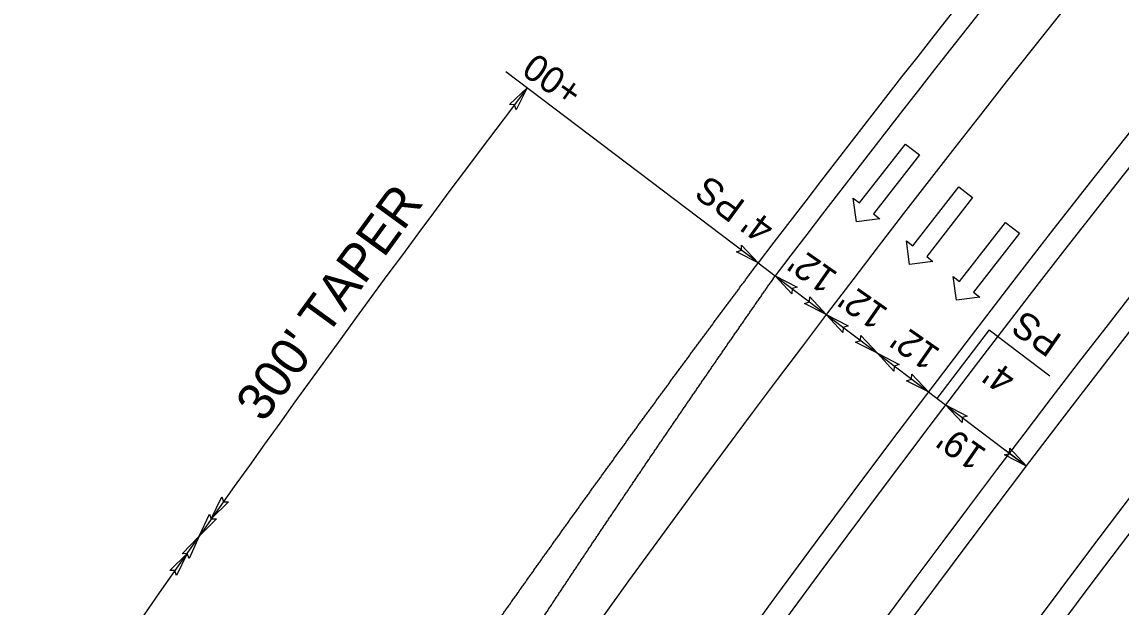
# Model space of a CAD drawing. Extents: x 2389099 to 2405615, y 552200 to 573532.
# Drawn here: x 2400552.8 to 2400758.8, y 569760.3 to 569869.9 of the extents above; entities that cross this region are included whole.
import ezdxf

# ---------------------------------------------------------------- set-up
doc = ezdxf.new("R2010")
doc.units = 0
for name, color, linetype in [('Prop Cable Guiderail Single Face', 7, 'Continuous'), ('Prop Dimension', 7, 'Continuous'), ('Prop Dimension Text', 7, 'Continuous'), ('Prop EOT', 7, 'Continuous'), ('Prop Horizontal Alignment', 7, 'Continuous'), ('Prop Horizontal Alignment Tick Small', 7, 'Continuous'), ('Prop Lane Arrow Through CELL', 7, 'Continuous'), ('Prop Lane Lines', 7, 'Continuous')]:
    doc.layers.add(name, color=color, linetype=linetype)

msp = doc.modelspace()

# ---------------------------------------------------------------- linework, layer by layer
at = {"layer": 'Prop Cable Guiderail Single Face'}
msp.add_arc((2403051.7, 568034.46), 2904, 119.41161, 162.0892, dxfattribs=at)
at = {"layer": 'Prop Dimension'}
for p, q in [((2400690.71, 569824.73), (2400643.46, 569860.55)), ((2400690.71, 569824.73), (2400693.89, 569822.31)), ((2400693.89, 569822.31), (2400703.45, 569815.06)), ((2400703.45, 569815.06), (2400713.02, 569807.81)), ((2400733.93, 569812.21), (2400724.17, 569799.35)), ((2400733.93, 569812.21), (2400745.34, 569803.56)), ((2400713.02, 569807.81), (2400722.58, 569800.56)), ((2400722.58, 569800.56), (2400725.77, 569798.14)), ((2400725.77, 569798.14), (2400740.91, 569786.66))]:
    msp.add_line(p, q, dxfattribs=at)
for points in [[(2400644.12, 569854.41), (2400647.45, 569857.52), (2400645.36, 569853.43), (2400645.07, 569854.38)], [(2400687.59, 569828.06), (2400690.71, 569824.73), (2400686.62, 569826.82), (2400687.56, 569827.11)], [(2400697.01, 569818.97), (2400693.89, 569822.31), (2400697.98, 569820.21), (2400697.04, 569819.92)], [(2400700.34, 569818.4), (2400703.45, 569815.06), (2400699.37, 569817.16), (2400700.31, 569817.45)], [(2400706.57, 569811.72), (2400703.45, 569815.06), (2400707.54, 569812.96), (2400706.6, 569812.67)], [(2400709.9, 569811.15), (2400713.02, 569807.81), (2400708.93, 569809.91), (2400709.87, 569810.2)], [(2400716.13, 569804.47), (2400713.02, 569807.81), (2400717.11, 569805.71), (2400716.16, 569805.42)], [(2400719.46, 569803.9), (2400722.58, 569800.56), (2400718.49, 569802.66), (2400719.43, 569802.95)], [(2400728.88, 569794.81), (2400725.77, 569798.14), (2400729.85, 569796.05), (2400728.91, 569795.76)], [(2400737.79, 569790), (2400740.91, 569786.66), (2400736.82, 569788.76), (2400737.76, 569789.05)], [(2400591.53, 569779.99), (2400588.3, 569776.76), (2400590.26, 569780.92), (2400590.58, 569779.99)], [(2400589.25, 569776.77), (2400586.02, 569773.54), (2400587.98, 569777.69), (2400588.3, 569776.76)], [(2400582.85, 569770.25), (2400586.02, 569773.54), (2400584.14, 569769.35), (2400583.8, 569770.27)], [(2400580.52, 569767.1), (2400583.8, 569770.27), (2400581.77, 569766.15), (2400581.47, 569767.08)]]:
    msp.add_lwpolyline(points, close=True, dxfattribs=at)
msp.add_arc((2403051.7, 568034.46), 3017.28, 142.82813, 148.75528, dxfattribs=at)
at = {"layer": 'Prop EOT'}
for radius, start, end in [(2923, 119.41161, 180.94658), (2919, 119.41161, 162.43732), (2881, 119.41161, 165.38993), (2877, 119.41161, 180.94658), (2963, 136.77855, 142.82813), (2959, 136.77855, 142.82813)]:
    msp.add_arc((2403051.7, 568034.46), radius, start, end, dxfattribs=at)
for points in [[(2400654.5, 569775.27), (2400654.98, 569775.94), (2400655.46, 569776.61), (2400655.94, 569777.28), (2400656.43, 569777.95), (2400656.91, 569778.63), (2400657.39, 569779.3), (2400657.88, 569779.98), (2400658.36, 569780.65), (2400658.85, 569781.32), (2400659.33, 569781.99), (2400659.81, 569782.67), (2400660.3, 569783.34), (2400660.78, 569784.01), (2400661.27, 569784.68), (2400661.75, 569785.35), (2400662.24, 569786.02), (2400662.72, 569786.69), (2400663.21, 569787.36), (2400663.7, 569788.04), (2400664.18, 569788.71), (2400664.67, 569789.38), (2400665.16, 569790.05), (2400665.64, 569790.72), (2400666.13, 569791.39), (2400666.61, 569792.06), (2400667.1, 569792.73), (2400667.59, 569793.4), (2400668.07, 569794.07), (2400668.56, 569794.73), (2400669.05, 569795.4), (2400669.54, 569796.08), (2400670.03, 569796.75), (2400670.52, 569797.42), (2400671.01, 569798.09), (2400671.5, 569798.75), (2400671.98, 569799.42), (2400672.47, 569800.09), (2400672.96, 569800.76), (2400673.45, 569801.42), (2400673.94, 569802.09), (2400674.43, 569802.76), (2400674.92, 569803.43), (2400675.41, 569804.09), (2400675.91, 569804.77), (2400676.4, 569805.44), (2400676.89, 569806.1), (2400677.38, 569806.77), (2400677.87, 569807.43), (2400678.36, 569808.1), (2400678.85, 569808.77), (2400679.34, 569809.43), (2400679.83, 569810.1), (2400680.32, 569810.76), (2400680.82, 569811.43), (2400681.31, 569812.1), (2400681.81, 569812.77), (2400682.3, 569813.43), (2400682.79, 569814.1), (2400683.28, 569814.76), (2400683.78, 569815.43), (2400684.27, 569816.09), (2400684.76, 569816.76), (2400685.26, 569817.42), (2400685.75, 569818.09), (2400686.25, 569818.75), (2400686.74, 569819.41), (2400687.23, 569820.08), (2400687.73, 569820.75), (2400688.23, 569821.41), (2400688.72, 569822.08), (2400689.22, 569822.74), (2400689.71, 569823.4), (2400690.71, 569824.73)], [(2400659.35, 569771.74), (2400659.81, 569772.43), (2400660.27, 569773.11), (2400660.73, 569773.8), (2400661.19, 569774.49), (2400661.65, 569775.17), (2400662.11, 569775.86), (2400662.58, 569776.56), (2400663.04, 569777.24), (2400663.5, 569777.93), (2400663.96, 569778.61), (2400664.42, 569779.3), (2400664.88, 569779.99), (2400665.34, 569780.67), (2400665.8, 569781.36), (2400666.27, 569782.04), (2400666.73, 569782.73), (2400667.19, 569783.41), (2400667.65, 569784.1), (2400668.12, 569784.79), (2400668.58, 569785.48), (2400669.05, 569786.16), (2400669.51, 569786.85), (2400669.97, 569787.53), (2400670.44, 569788.22), (2400670.9, 569788.9), (2400671.36, 569789.58), (2400671.83, 569790.27), (2400672.29, 569790.95), (2400672.76, 569791.64), (2400673.22, 569792.32), (2400673.69, 569793.01), (2400674.16, 569793.69), (2400674.62, 569794.38), (2400675.09, 569795.06), (2400675.56, 569795.74), (2400676.02, 569796.43), (2400676.49, 569797.11), (2400676.95, 569797.79), (2400677.42, 569798.47), (2400677.89, 569799.16), (2400678.35, 569799.84), (2400678.82, 569800.52), (2400679.29, 569801.2), (2400679.76, 569801.89), (2400680.23, 569802.58), (2400680.7, 569803.26), (2400681.17, 569803.94), (2400681.64, 569804.62), (2400682.1, 569805.3), (2400682.57, 569805.98), (2400683.04, 569806.66), (2400683.51, 569807.35), (2400683.98, 569808.03), (2400684.45, 569808.71), (2400684.92, 569809.39), (2400685.39, 569810.08), (2400685.87, 569810.76), (2400686.34, 569811.44), (2400686.81, 569812.12), (2400687.28, 569812.8), (2400687.75, 569813.48), (2400688.22, 569814.16), (2400688.69, 569814.84), (2400689.16, 569815.52), (2400689.63, 569816.19), (2400690.1, 569816.87), (2400690.58, 569817.55), (2400691.06, 569818.24), (2400691.53, 569818.92), (2400692, 569819.6), (2400692.47, 569820.28), (2400692.95, 569820.95), (2400693.89, 569822.31)], [(2400619.32, 569725.07), (2400619.79, 569725.75), (2400620.26, 569726.44), (2400620.73, 569727.12), (2400621.2, 569727.8), (2400621.67, 569728.48), (2400622.13, 569729.16), (2400622.61, 569729.85), (2400623.08, 569730.53), (2400623.55, 569731.22), (2400624.02, 569731.9), (2400624.49, 569732.58), (2400624.96, 569733.26), (2400625.43, 569733.94), (2400625.9, 569734.62), (2400626.37, 569735.3), (2400626.84, 569735.98), (2400627.31, 569736.66), (2400627.78, 569737.34), (2400628.26, 569738.03), (2400628.73, 569738.71), (2400629.2, 569739.39), (2400629.67, 569740.07), (2400630.15, 569740.75), (2400630.62, 569741.43), (2400631.09, 569742.11), (2400631.56, 569742.79), (2400632.04, 569743.47), (2400632.51, 569744.15), (2400632.98, 569744.82), (2400633.46, 569745.5), (2400633.93, 569746.19), (2400634.41, 569746.87), (2400634.88, 569747.55), (2400635.36, 569748.22), (2400635.83, 569748.9), (2400636.31, 569749.58), (2400636.78, 569750.26), (2400637.26, 569750.94), (2400637.73, 569751.61), (2400638.21, 569752.29), (2400638.68, 569752.97), (2400639.16, 569753.64), (2400639.63, 569754.32), (2400640.11, 569755.01), (2400640.59, 569755.68), (2400641.07, 569756.36), (2400641.54, 569757.04), (2400642.02, 569757.71), (2400642.5, 569758.39), (2400642.98, 569759.06), (2400643.45, 569759.74), (2400643.93, 569760.42), (2400644.41, 569761.09), (2400644.89, 569761.77), (2400645.36, 569762.44), (2400645.85, 569763.13), (2400646.33, 569763.8), (2400646.81, 569764.48), (2400647.28, 569765.15), (2400647.76, 569765.83), (2400648.24, 569766.5), (2400648.72, 569767.17), (2400649.2, 569767.85), (2400649.68, 569768.52), (2400650.16, 569769.2), (2400650.64, 569769.87), (2400651.12, 569770.54), (2400651.61, 569771.23), (2400652.09, 569771.9), (2400652.57, 569772.57), (2400653.05, 569773.25), (2400653.53, 569773.92), (2400654.02, 569774.59), (2400654.5, 569775.27)], [(2400625.89, 569720.5), (2400626.34, 569721.2), (2400626.78, 569721.9), (2400627.23, 569722.59), (2400627.67, 569723.29), (2400628.12, 569723.98), (2400628.56, 569724.68), (2400629.01, 569725.38), (2400629.46, 569726.08), (2400629.91, 569726.77), (2400630.35, 569727.47), (2400630.8, 569728.16), (2400631.25, 569728.86), (2400631.69, 569729.55), (2400632.14, 569730.25), (2400632.59, 569730.94), (2400633.03, 569731.64), (2400633.48, 569732.33), (2400633.93, 569733.02), (2400634.38, 569733.73), (2400634.83, 569734.42), (2400635.28, 569735.11), (2400635.73, 569735.81), (2400636.18, 569736.5), (2400636.63, 569737.19), (2400637.08, 569737.89), (2400637.52, 569738.58), (2400637.97, 569739.27), (2400638.42, 569739.96), (2400638.87, 569740.66), (2400639.32, 569741.35), (2400639.78, 569742.05), (2400640.23, 569742.74), (2400640.68, 569743.44), (2400641.13, 569744.13), (2400641.58, 569744.82), (2400642.04, 569745.51), (2400642.49, 569746.2), (2400642.94, 569746.9), (2400643.39, 569747.59), (2400643.84, 569748.28), (2400644.29, 569748.97), (2400644.75, 569749.66), (2400645.2, 569750.35), (2400645.66, 569751.05), (2400646.11, 569751.74), (2400646.57, 569752.43), (2400647.02, 569753.12), (2400647.47, 569753.81), (2400647.93, 569754.5), (2400648.38, 569755.19), (2400648.84, 569755.88), (2400649.29, 569756.57), (2400649.74, 569757.26), (2400650.2, 569757.95), (2400650.65, 569758.64), (2400651.12, 569759.34), (2400651.57, 569760.03), (2400652.03, 569760.72), (2400652.48, 569761.41), (2400652.94, 569762.1), (2400653.4, 569762.79), (2400653.85, 569763.48), (2400654.31, 569764.16), (2400654.77, 569764.85), (2400655.22, 569765.54), (2400655.68, 569766.23), (2400656.14, 569766.92), (2400656.6, 569767.61), (2400657.06, 569768.3), (2400657.52, 569768.99), (2400657.98, 569769.68), (2400658.43, 569770.36), (2400658.89, 569771.05), (2400659.35, 569771.74)]]:
    msp.add_spline(points, degree=3, dxfattribs=at)
at = {"layer": 'Prop Horizontal Alignment'}
msp.add_arc((2403051.7, 568034.46), 2900, 119.41161, 180.94658, dxfattribs=at)
at = {"layer": 'Prop Horizontal Alignment Tick Small'}
msp.add_line((2400740.91, 569786.66), (2400736.92, 569789.68), dxfattribs=at)
at = {"layer": 'Prop Lane Arrow Through CELL'}
for p, q in [((2400709.68, 569835.97), (2400718.28, 569847.01)), ((2400718.28, 569847.01), (2400720.88, 569844.99)), ((2400720.88, 569844.99), (2400712.28, 569833.94)), ((2400719.64, 569827.97), (2400728.25, 569839.01)), ((2400728.25, 569839.01), (2400730.85, 569836.99)), ((2400730.85, 569836.99), (2400722.25, 569825.94)), ((2400709.08, 569832.44), (2400708.49, 569836.89)), ((2400708.49, 569836.89), (2400709.68, 569835.97)), ((2400713.46, 569833.02), (2400709.08, 569832.44)), ((2400712.28, 569833.94), (2400713.46, 569833.02)), ((2400728.4, 569821.28), (2400737.01, 569832.32)), ((2400737.01, 569832.32), (2400739.61, 569830.29)), ((2400719.05, 569824.44), (2400718.46, 569828.89)), ((2400718.46, 569828.89), (2400719.64, 569827.97)), ((2400739.61, 569830.29), (2400731.01, 569819.25)), ((2400723.43, 569825.02), (2400719.05, 569824.44)), ((2400722.25, 569825.94), (2400723.43, 569825.02)), ((2400727.81, 569817.75), (2400727.22, 569822.2)), ((2400727.22, 569822.2), (2400728.4, 569821.28)), ((2400731.01, 569819.25), (2400732.19, 569818.33)), ((2400732.19, 569818.33), (2400727.81, 569817.75))]:
    msp.add_line(p, q, dxfattribs=at)
at = {"layer": 'Prop Lane Lines'}
for radius, start, end in [(2947, 129.29029, 148.75528), (2853, 131.16509, 154.68244)]:
    msp.add_arc((2403051.7, 568034.46), radius, start, end, dxfattribs=at)

# ---------------------------------------------------------------- texts
at = {"layer": 'Prop Dimension Text'}
for s, height, rotation, p in [('+00', 5, 145.0071, (2400658.3, 569857.8)), ("4' PS", 5, 143.8029, (2400694.1, 569832.02)), ("300' TAPER", 7, 53.9799, (2400598.09, 569794.62)), ("12'", 5, 145.1622, (2400705.86, 569822.74)), ("12'", 5, 145.1622, (2400715.3, 569815.98)), ('PS', 5, 145.1622, (2400747.86, 569810.95)), ("12'", 5, 145.1622, (2400725.06, 569808.37)), ("4'", 5, 145.1622, (2400739.3, 569803.89)), ("19'", 5, 145.1622, (2400733.73, 569789.58))]:
    msp.add_text(s, height=height, rotation=rotation, dxfattribs=at).set_placement(p)

doc.saveas('drawing.dxf')
